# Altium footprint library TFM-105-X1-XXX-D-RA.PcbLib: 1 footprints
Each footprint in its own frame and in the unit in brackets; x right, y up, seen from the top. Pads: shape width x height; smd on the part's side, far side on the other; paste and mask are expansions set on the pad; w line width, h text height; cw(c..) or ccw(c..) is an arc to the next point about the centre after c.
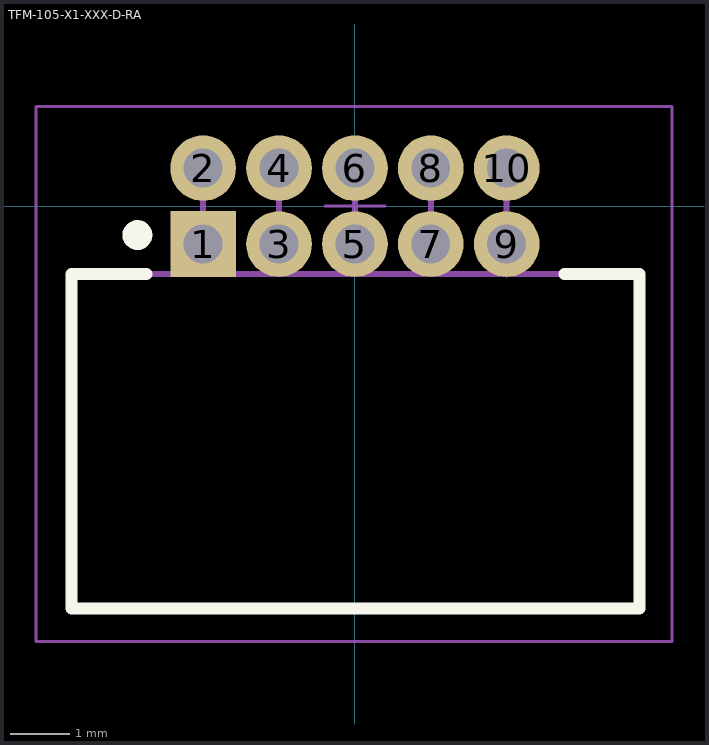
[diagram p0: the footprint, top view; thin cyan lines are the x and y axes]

## TFM-105-X1-XXX-D-RA [mm] "1.27mm pitch, 5 pin, terminal strip; r/a, double row"
height 5.72
pads (10):
  rect 1.1x1.1 hole 0.65 mask+0: 1(-2.54,-0.635)
  round 1.1 hole 0.65 mask+0: 2(-2.54,0.635) 3(-1.27,-0.635) 4(-1.27,0.635) 5(0,-0.635) 6(0,0.635) 7(1.27,-0.635) 8(1.27,0.635) 9(2.54,-0.635) 10(2.54,0.635)
Top Overlay:
  circle w0.25: c-3.64,-0.485 r0.125
  lines w0.2: -3.49,-1.135 -4.74,-1.135 -4.74,-6.735 4.76,-6.735 4.76,-1.135 3.51,-1.135
Mechanical 12:
  lines w0.001: -2.54,-1.135 -2.54,0.635 ; -1.27,-1.135 -1.27,0.635 ; 0,-1.135 0,0.635 ; 1.27,-1.135 1.27,0.635 ; 2.54,-1.143 2.54,0.635 ; -4.74,-6.735 4.76,-6.735 4.76,-1.135 -4.74,-1.135 -4.74,-6.735
Mechanical 13:
  lines w0.1: -2.54,-1.135 -2.54,0.635 ; -1.27,-1.135 -1.27,0.635 ; 0,-1.135 0,0.635 ; 1.27,-1.135 1.27,0.635 ; 2.54,-1.143 2.54,0.635 ; -4.74,-6.735 4.76,-6.735 4.76,-1.135 -4.74,-1.135 -4.74,-6.735
  text ".Designator" at 0,-0.127 h1.52
Mechanical 15:
  lines w0.05: -0.5,0 0.5,0 ; 0,-0.5 0,0.5 ; -5.34,-7.285 5.31,-7.285 5.31,1.665 -5.34,1.665 -5.34,-7.285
